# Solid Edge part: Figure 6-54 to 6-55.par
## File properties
Author: CADCIM
Template: normal.par
Last saved by: CADCIM
Revision: 5
Application: Solid Edge
Accuracy: 0.99
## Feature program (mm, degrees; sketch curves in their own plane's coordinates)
sketch for "unnamed Protrusion 1" plane through (0, 0, 0) normal (0, 0, 1) x-axis (1, 0, 0)
  line (-57.5394, -77.0624) -> (57.5394, -77.0624)
  line (57.5394, -77.0624) -> (57.5394, 41.189)
  line (57.5394, 41.189) -> (-57.5394, 41.189)
  line (-57.5394, 41.189) -> (-57.5394, -77.0624)
extrude "unnamed Protrusion 1" add finite 19.05 along +normal
sketch for "Hole_1" plane through (0, 0, 19.05) normal (0, 0, 1) x-axis (1, 0, 0)
  hole centre (-47.4962, -26.782) bore radius 3.175
hole "Hole_1" diameter 6.35 through  CounterBoreDepth = 2 mm
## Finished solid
Body 1: solid body, 9 faces, 16 edges, 8 vertices.
  Faces by surface: plane 7, cylinder 2
  Edges by curve: line 12, circle 4
Bounding box of the edges (mm): 115.079 x 118.251 x 19.050, from (-57.5394, -77.0624, 0) to (57.5394, 41.189, 19.05).
Cylindrical faces by radius (mm): R3.175 x1, R6.35 x1
Planar faces by outward normal: +x 1, +y 1, +z 2, -x 1, -y 1, -z 1
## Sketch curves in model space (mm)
line (-47.821, -27.0372, 19.05) -> (-34.8186, -40.2964, 19.05)
spline (-47.821, -27.0372, 19.05) -> (43.5628, 9.9651, 19.05) -> (-43.116, 9.1379, 19.05)
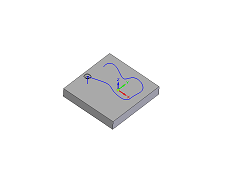
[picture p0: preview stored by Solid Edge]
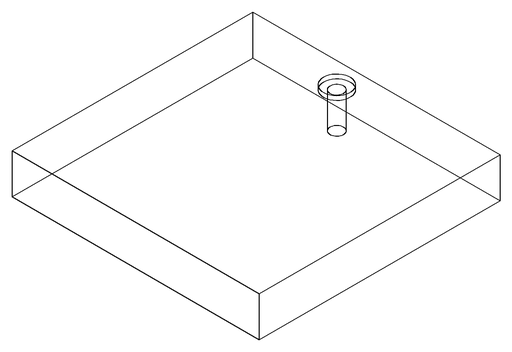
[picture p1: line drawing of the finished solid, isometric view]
